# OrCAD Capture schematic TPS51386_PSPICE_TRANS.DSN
size C; title: TPS51386 4.5-V to 24-V, 8-A Synchronous Buck Converter; rev: 1.0; note: Datasheet: SLUSF01         EVM: SLUUCN0A; note: Synchronous Step Down Converter; note: with 100mA LDO
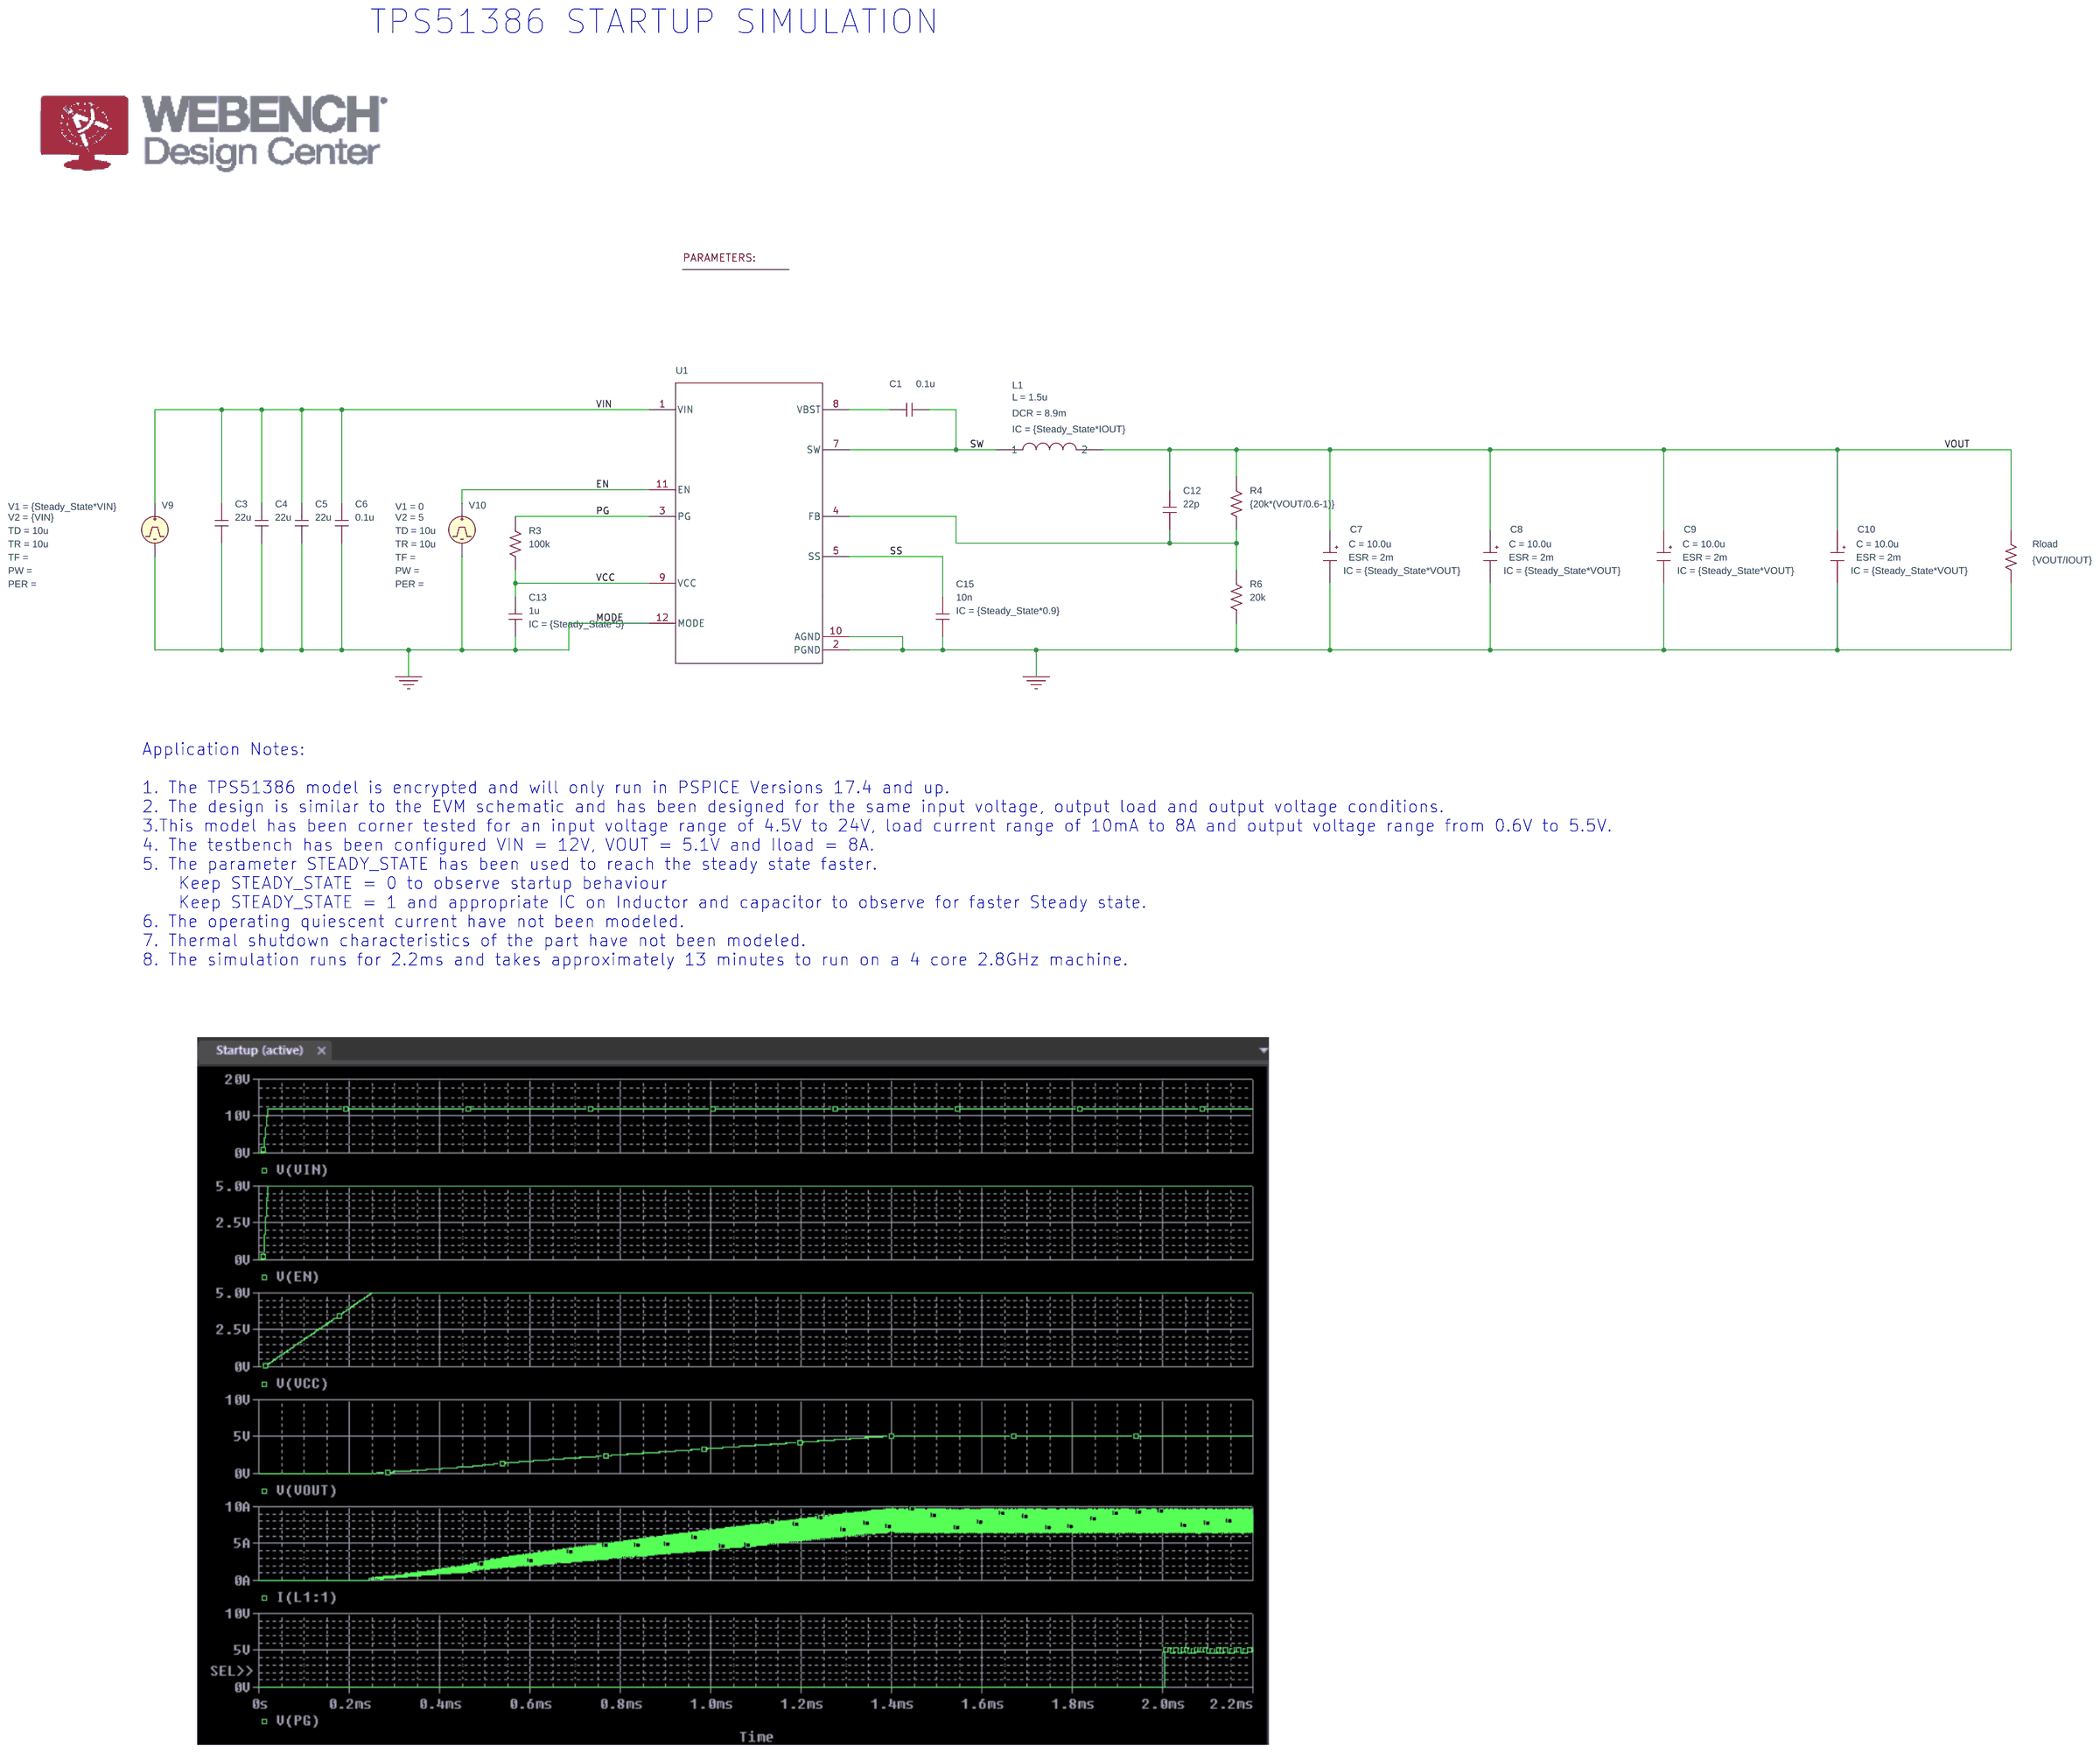
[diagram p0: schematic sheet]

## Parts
3  PARAM
C1  0.1u  [RAD/CK05]
C3  22u  [RAD/CK05]
C4  22u  [RAD/CK05]
C5  22u  [RAD/CK05]
C6  0.1u  [RAD/CK05]
C7  CESR
C8  CESR
C9  CESR
C10  CESR
C12  22p  [RAD/CK05]
C13  1u  [RAD/CK05]
C15  10n  [RAD/CK05]
L1  LDCR
R3  100k  [AX/RC05]
R4  {20k*(VOUT/0.6-1)}  [AX/RC05]
R6  20k  [AX/RC05]
Rload  {VOUT/IOUT}  [AX/RC05]
U1  Value  [RJN0012A-MFG]
V9  VPULSE
V10  VPULSE

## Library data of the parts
3 = PARAM: IOUT: 8; Steady_State: 0; VIN: 12; VOUT: 5.1
C1 = C: IC: 0
C3-C6 = C: IC: {Steady_State*VIN}
C7-C10 = CESR_0: C: 10.0u; ESL: 0; ESR: 2m; IC: {Steady_State*VOUT}
C12 = C: IC: {Steady_State*(VOUT-0.6)}
C13 = C: IC: {Steady_State*5}
C15 = C: IC: {Steady_State*0.9}
L1 = LDCR: DCR: 8.9m; IC: {Steady_State*IOUT}; L: 1.5u
R3 R4 R6 Rload = R
U1 = TPS51386RJN_TRANS
V9 = VPULSE: TD: 10u; TR: 10u; V1: {Steady_State*VIN}; V2: {VIN}
V10 = VPULSE: TD: 10u; TR: 10u; V1: 0; V2: 5

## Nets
VCC: C13.2 R3.2 U1.9(VCC)
VIN: C3.1 C4.1 C5.1 C6.1 U1.1(VIN) V9.1(+)
0: C3.2 C4.2 C5.2 C6.2 C7.2(OUT) C8.2(OUT) C9.2(OUT) C10.2(OUT) C13.1 C15.2 R6.2 Rload.2 U1.2(PGND) U1.10(AGND) U1.12(MODE) V9.2(-) V10.2(-)
EN: U1.11(EN) V10.1(+)
PG: R3.1 U1.3(PG)
SS: C15.1 U1.5(SS)
SW: C1.1 L1.1 U1.7(SW)
VOUT: C7.1(IN) C8.1(IN) C9.1(IN) C10.1(IN) C12.2 L1.2 R4.1 Rload.1
N02756: C1.2 U1.8(VBST)
N04744: C12.1 R4.2 R6.1 U1.4(FB)

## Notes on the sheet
- TPS51386 STARTUP SIMULATION
- Application Notes:
  1. The TPS51386 model is encrypted and will only run in PSPICE Versions 17.4 and up.
  2. The design is similar to the EVM schematic and has been designed for the same input voltage, output load and output voltage conditions.
  3.This model has been corner tested for an input voltage range of 4.5V to 24V, load current range of 10mA to 8A and output voltage range from 0.6V to 5.5V.
  4. The testbench has been configured VIN = 12V, VOUT = 5.1V and Iload = 8A.
  5. The parameter STEADY_STATE has been used to reach the steady state faster.
      Keep STEADY_STATE = 0 to observe startup behaviour
      Keep STEADY_STATE = 1 and appropriate IC on Inductor and capacitor to observe for faster Steady state.
  6. The operating quiescent current have not been modeled.
  7. Thermal shutdown characteristics of the part have not been modeled.
  8. The simulation runs for 2.2ms and takes approximately 13 minutes to run on a 4 core 2.8GHz machine.
